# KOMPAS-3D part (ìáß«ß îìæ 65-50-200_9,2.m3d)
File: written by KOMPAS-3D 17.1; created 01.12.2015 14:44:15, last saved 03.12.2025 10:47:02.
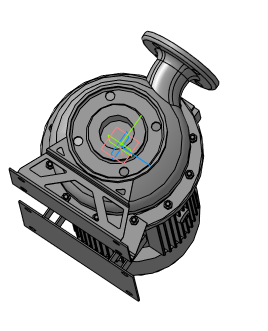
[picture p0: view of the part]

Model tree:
1. Операция без истории:3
